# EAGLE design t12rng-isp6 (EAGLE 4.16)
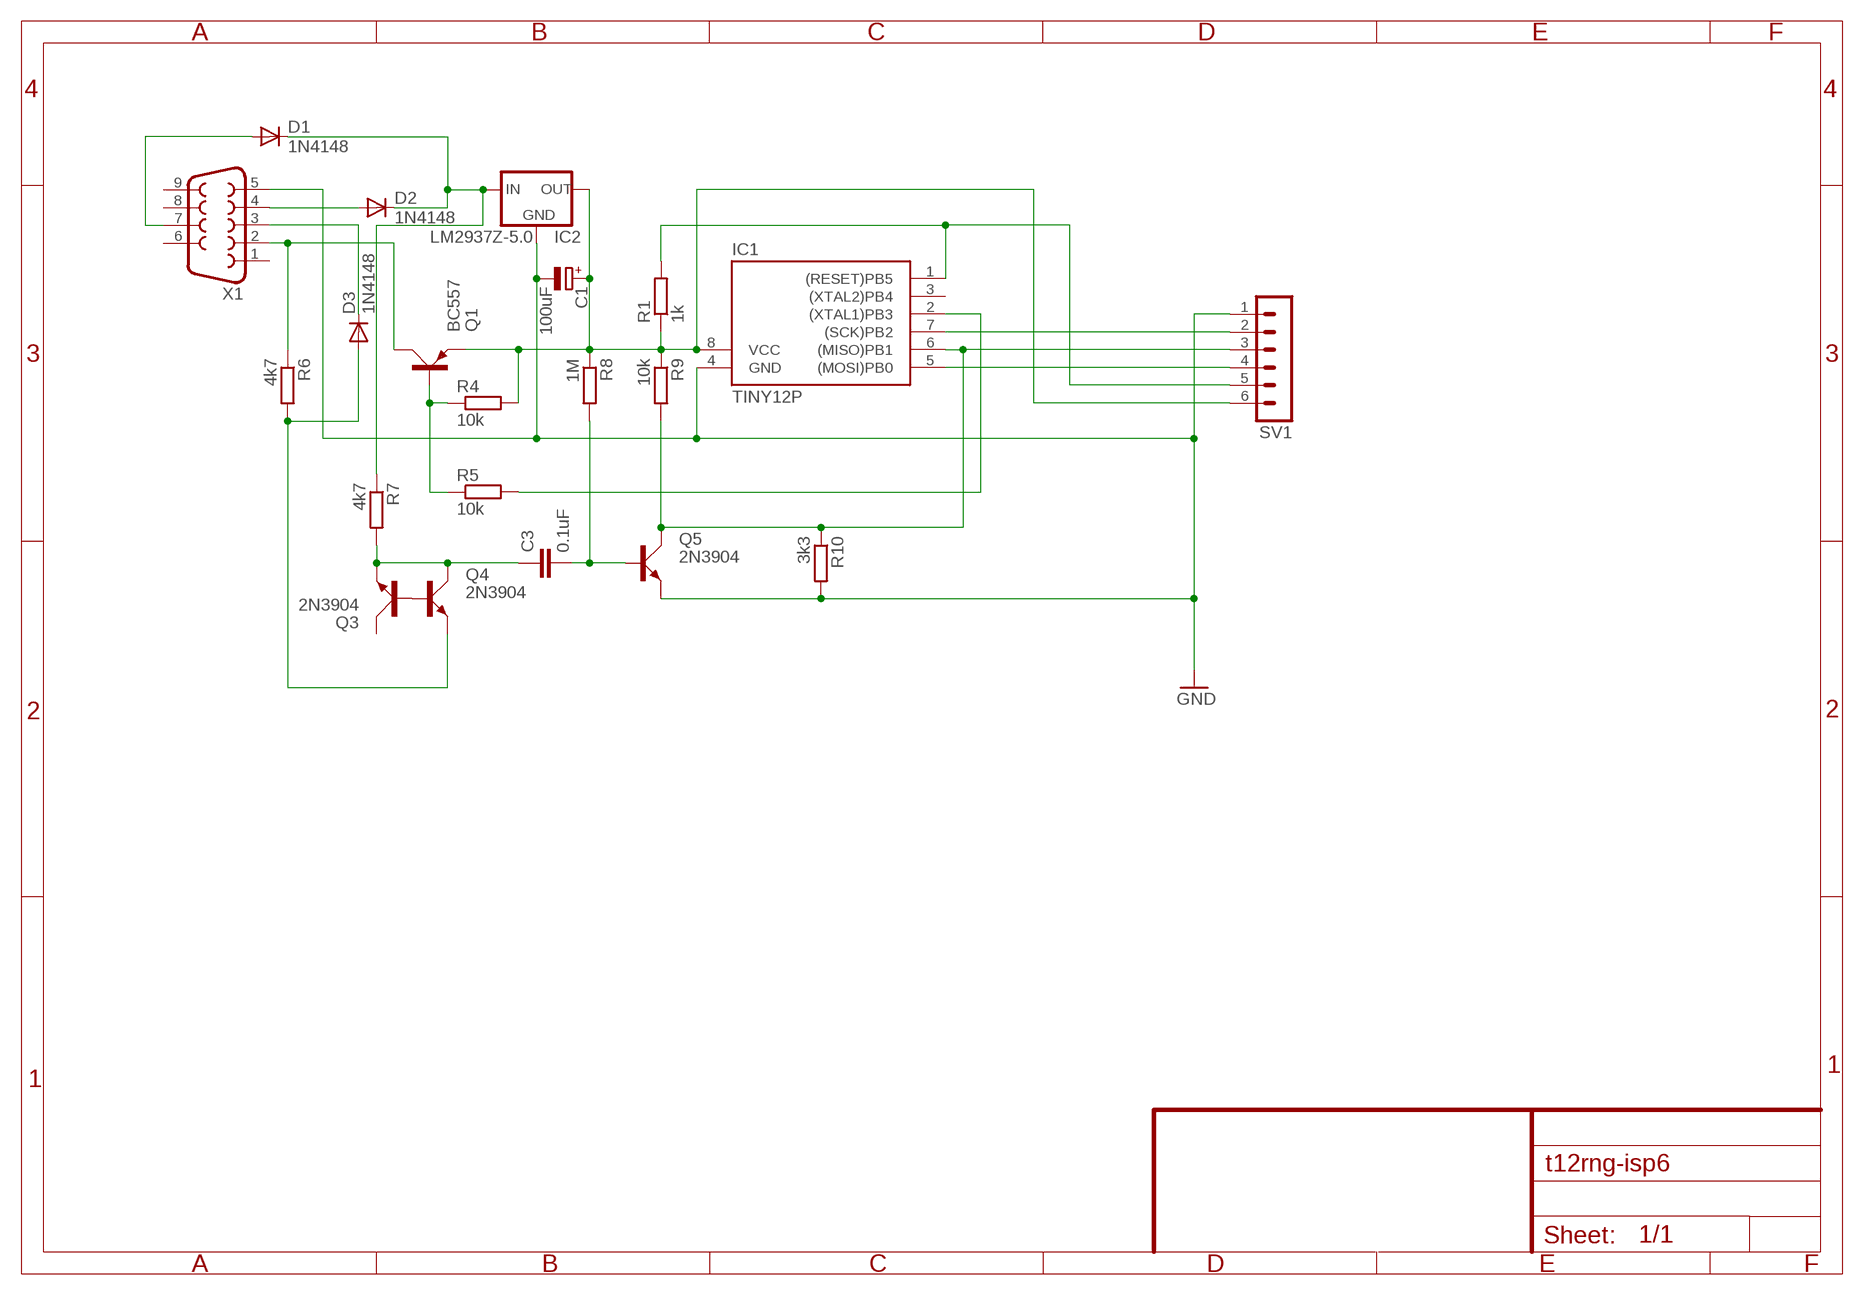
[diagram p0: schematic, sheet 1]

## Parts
C1  100uF  CPOL-EUE3.5-8  [E3,5-8]
C3  0.1uF  C-EU075-032X103  [C075-032X103]
D1  1N4148  DIODE-D-2.5  [D-2.5]
D2  1N4148  DIODE-D-2.5  [D-2.5]
D3  1N4148  DIODE-D-2.5  [D-2.5]
IC1  TINY12P  [DIL08]
IC2  LM2937Z-5.0  78LXX  [78LXX]
Q1  BC557  [SOT54A]
Q3  2N3904  [TO92D]
Q4  2N3904  [TO92D]
Q5  2N3904  [TO92D]
R1  1k  R-EU_0207/2V  [0207/2V]
R4  10k  R-EU_0207/2V  [0207/2V]
R5  10k  R-EU_0207/2V  [0207/2V]
R6  4k7  R-EU_0207/2V  [0207/2V]
R7  4k7  R-EU_0207/2V  [0207/2V]
R8  1M  R-EU_0207/2V  [0207/2V]
R9  10k  R-EU_0207/2V  [0207/2V]
R10  3k3  R-EU_0207/2V  [0207/2V]
SV1  MA06-1  [MA06-1]
X1  F09H  [F09H]

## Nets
GND: C1.- IC1.4(GND) IC2.GND Q5.E R10.2 SV1.1 X1.5
N$1: IC1.7((SCK)PB2) SV1.2
N$2: IC1.5((MOSI)PB0) SV1.4
N$3: D1.A X1.7
N$4: D2.A X1.4
N$5: D1.C D2.C IC2.IN R7.1
N$6: C1.+ IC1.8(VCC) IC2.OUT Q1.E R1.1 R4.2 R8.1 R9.1 SV1.6
N$7: IC1.1((RESET)PB5) R1.2 SV1.5
N$9: D3.A Q4.E R6.2
N$10: Q1.B R4.1 R5.1
N$11: IC1.2((XTAL1)PB3) R5.2
N$12: Q1.C R6.1 X1.2
N$13: D3.C X1.3
N$14: Q3.B Q4.B
N$15: C3.1 Q3.E Q4.C R7.2
N$17: C3.2 Q5.B R8.2
N$18: IC1.6((MISO)PB1) Q5.C R9.2 R10.1 SV1.3
Unconnected: IC1.3((XTAL2)PB4) Q3.C X1.1 X1.6 X1.8 X1.9

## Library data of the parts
C1 = rcl:CPOL-EU: POLARIZED CAPACITOR, European symbol
C3 = rcl:C-EU: CAPACITOR, European symbol
D1-D3 = diode:DIODE-: DIODE
IC1 = atmel:TINY12*: MICROCONTROLLER 1 Kbytes FLASH 64 bytes EEPROM
IC2 = v-reg:78LXX: VOLTAGE REGULATOR
Q1 = transistor-small-signal:BC557: PNP TRANSISTOR
Q3-Q5 = transistor-small-signal:2N3904: NPN TRANSISTOR
R1 R4-R10 = rcl:R-EU_: RESISTOR, European symbol
SV1 = con-lstb:MA06-1: PIN HEADER
X1 = con-subd:F09: SUB-D

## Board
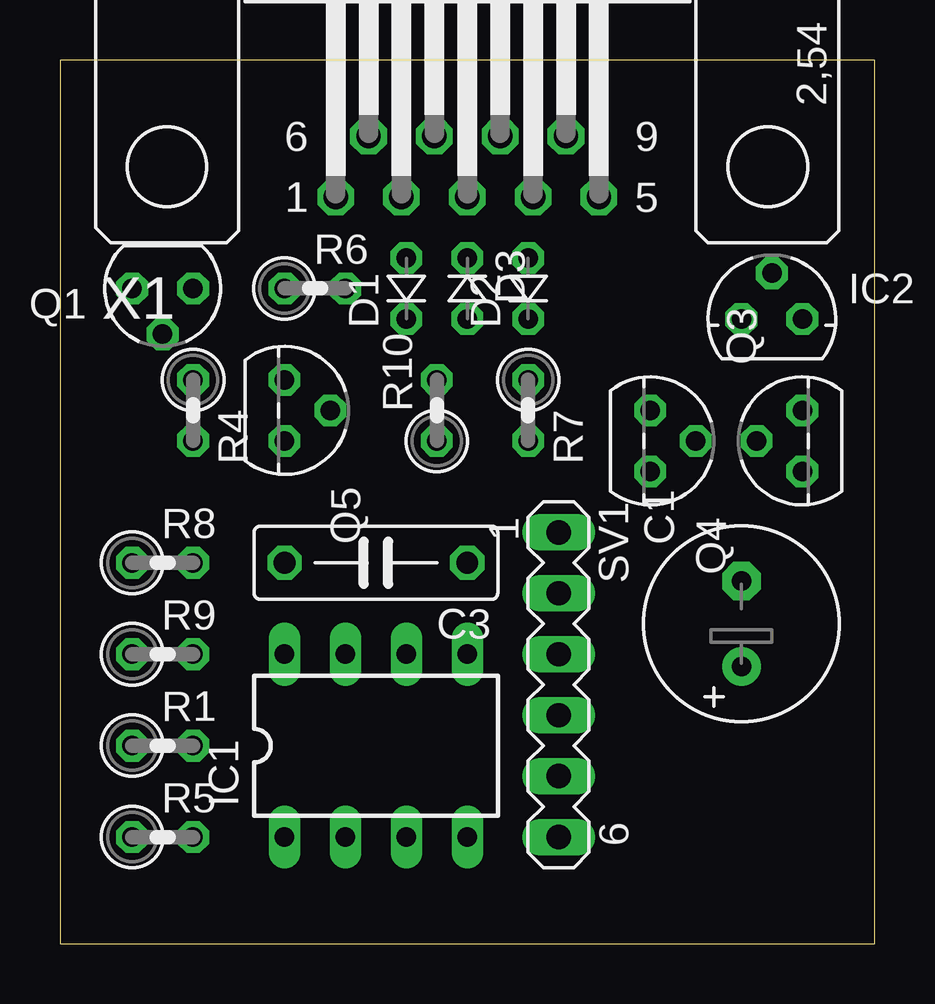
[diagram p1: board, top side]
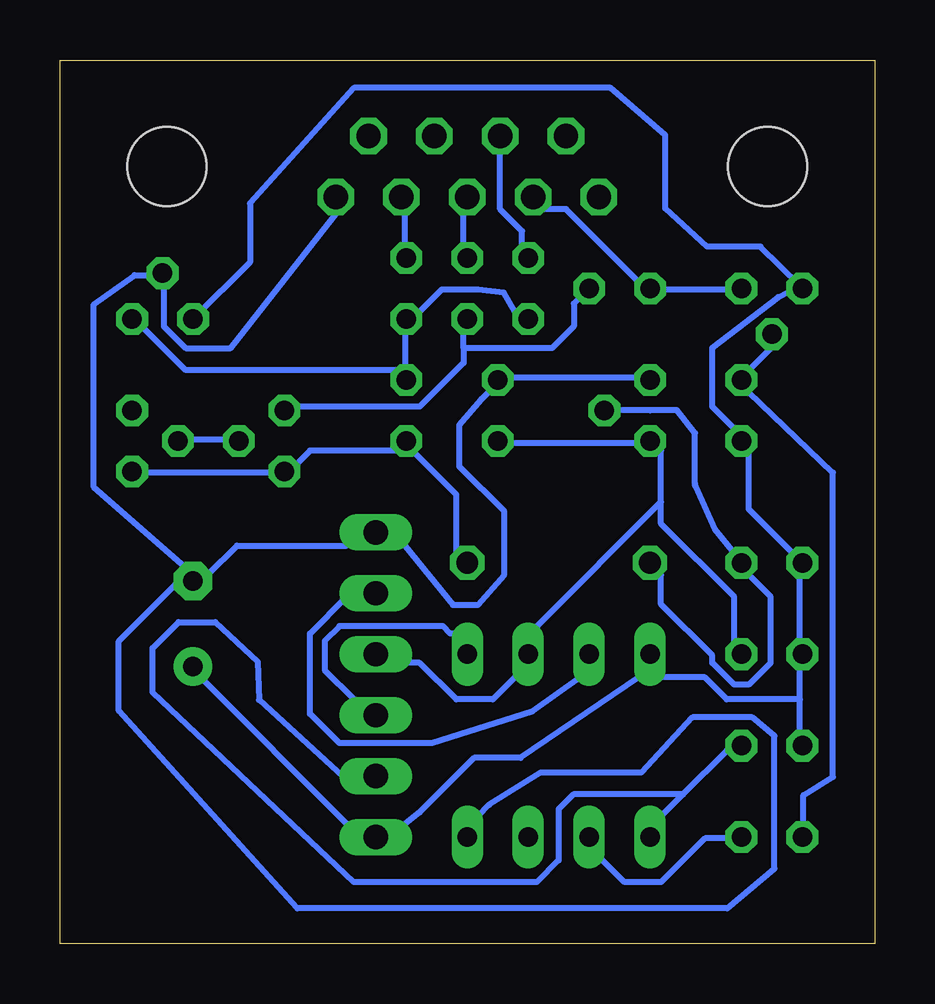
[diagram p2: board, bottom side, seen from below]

Size 33.96 x 36.82 mm. Coordinates in mm from the lower left corner, seen from the top.
Outline: 0,0 33.96,0 33.96,36.82 0,36.82 0,0
Copper layers (1*16): Top 0.035mm / dielectric 1.5mm / Bottom 0.035mm
Design rules "default": minimum track width 10mil, minimum drill 24mil, track to track 8mil, track to pad 8mil, pad to pad 8mil, via to via 8mil, smd to smd 8mil, copper to edge 40mil, drill to drill 8mil, minimum pad ring 10mil, minimum via ring 8mil, stop-mask expansion 4mil, vias tented up to drill 0mil, thermal gap 10mil

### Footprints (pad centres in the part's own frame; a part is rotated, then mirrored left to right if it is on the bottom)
E3,5-8 = drill 0.813 pad 1.6 round: + -1.778,0 | drill 0.813 pad 1.6 octagon: - 1.778,0
C075-032X103 = drill 0.914 octagon: 1 -3.81,0; 2 3.81,0
D-2.5 = drill 0.813 octagon: A 1.27,0; C -1.27,0
DIL08 = drill 0.813 long: 1 -3.81,-3.81; 2 -1.27,-3.81; 3 1.27,-3.81; 4 3.81,-3.81; 5 3.81,3.81; 6 1.27,3.81; 7 -1.27,3.81; 8 -3.81,3.81
78LXX = drill 0.813 octagon: GND 0,1.905; IN 1.27,0; OUT -1.27,0
SOT54A = drill 0.813 octagon: B 0,1.905; C -1.27,0; E 1.27,0
TO92D = drill 0.813 octagon: B 0,1.905; C 1.27,0; E -1.27,0
0207/2V = drill 0.813 octagon: 1 -1.27,0; 2 1.27,0
MA06-1 = drill 1.016 long: 1 -6.35,0; 2 -3.81,0; 3 -1.27,0; 4 1.27,0; 5 3.81,0; 6 6.35,0
F09H = drill 1.016 octagon: 1 -5.486,-1.27; 2 -2.743,-1.27; 3 0,-1.27; 4 2.743,-1.27; 5 5.486,-1.27; 6 -4.115,1.27; 7 -1.372,1.27; 8 1.372,1.27; 9 4.115,1.27 | hole 3.302: -12.522,0; 12.522,0

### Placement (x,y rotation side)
C1  28.41,13.33 90 top
C3  13.17,15.87 180 top
D1  14.44,27.3 90 top
D2  19.52,27.3 90 top
D3  16.98,27.3 270 top
IC1  13.17,8.25 0 top
IC2  29.68,26.03 0 top
Q1  4.28,27.3 180 top
Q3  30.95,20.95 90 top
Q4  24.6,20.95 270 top
Q5  9.36,22.22 270 top
R1  4.28,8.25 0 top
R4  5.55,22.22 270 top
R5  4.28,4.44 0 top
R6  10.63,27.3 0 top
R7  19.52,22.22 270 top
R8  4.28,15.87 0 top
R9  4.28,12.06 0 top
R10  15.71,22.22 90 top
SV1  20.79,10.79 270 top
X1  16.98,32.38 0 top

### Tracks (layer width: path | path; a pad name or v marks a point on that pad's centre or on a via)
GND
  Bottom 0.254: X1.5 22.31,30.6 26.84,24.81 28.71,24.81 29.63,25.73 29.63,27.55 IC2.GND 30.24,27.86 30.85,27.86 32.54,26.64 32.54,19.02 28.71,15.67 C1.- | Q5.E 9.82,23.59 15.3,23.59 R10.2 15.75,23.3 16.39,22.69 17.3,21.62 17.3,19.88 15.44,18.01 15.44,15.38 16.54,14.12 17.58,14.12 19.57,16.58 SV1.1 22.01,16.58 26.58,16.58 27.8,15.36 C1.- | IC1.4 16.52,5.3 16.07,5.78 13.93,7.13 9.72,7.13 7.59,9.42 5.1,9.42 4.17,8.66 4.17,3.13 6.15,1.47 24.07,1.47 31.51,9.7 31.51,12.61 29.03,15.08 C1.-
N$1
  Bottom 0.254: IC1.7 12.26,11.09 14.28,9.67 18.45,8.35 22.31,8.35 23.53,9.57 23.53,12.92 22.01,14.45 SV1.2
N$2
  Bottom 0.254: IC1.5 17.44,12.92 17.69,12.92 18,13.23 22.31,13.23 22.92,12.62 22.92,11.4 21.7,10.18 SV1.4
N$3
  Bottom 0.254: D1.A 14.69,29.08 14.69,29.69 15.61,30.6 X1.7
N$4
  Bottom 0.254: D2.A 19.57,29.08 19.57,30.6 X1.4
N$5
  Bottom 0.254: D1.C 15,26.34 15.45,27.13 16.52,27.25 18.05,27.25 18.96,26.34 D2.C 19.57,25.42 19.57,23.9 R7.1 19.88,23.9 28.71,23.9 30.54,25.73 IC2.IN
N$6
  Bottom 0.254: C1.+ 28.11,11.09 22.01,5 SV1.6 19.57,5 18.96,5.48 16.69,7.74 14.76,7.74 9.82,11.09 IC1.8 8.9,11.09 7.07,11.09 6.16,10.18 3.11,10.18 | 3.11,10.18 3.11,11.7 R9.1 3.11,12.62 3.11,15.36 R8.1 5.25,18.1 5.25,20.54 R4.2 5.86,21.46 6.77,22.37 6.77,24.82 4.01,26.94 3.09,27.42 | 3.11,10.18 3.11,8.66 R1.1 | 3.09,27.42 2.94,27.42 Q1.E | 3.09,27.42 4.76,29.05 6.98,29.05 8.73,30.63 8.73,33.69 11.01,35.66 21.7,35.66 26.04,30.85 26.04,28.39 IC2.OUT
N$7
  Bottom 0.254: 7.99,6.22 6.16,8.05 R1.2 | 7.99,6.22 8.9,5.3 IC1.1 | 7.99,6.22 12.56,6.22 13.17,5.61 13.17,3.48 14.08,2.56 21.7,2.56 30.11,10.48 30.11,12.31 29.02,13.4 27.48,13.4 25.71,11.74 25.67,10.16 22.16,6.96 21.69,6.96 SV1.5
N$9
  Bottom 0.254: 17.13,24.81 17.13,24.2 18.96,22.37 24.14,22.37 Q4.E | 17.13,24.81 17.13,25.42 D3.A | 17.13,24.81 13.45,24.81 12.54,25.73 12.54,26.66 R6.2
N$10
  Bottom 0.254: R5.1 2.97,5 2.97,6.19 1.73,6.95 1.73,19.63 5.25,22.98 R4.1 5.25,23.9 4.33,24.81 Q1.B
N$11
  Bottom 0.254: R5.2 6.16,4.39 7.07,4.39 8.9,2.56 10.43,2.56 11.34,3.48 IC1.2
N$12
  Bottom 0.254: Q1.C 6.16,27.25 8.9,27.25 R6.1 9.82,27.55 12.87,30.6 13.78,30.6 X1.2
N$13
  Bottom 0.254: D3.C 17.13,29.08 17.13,30.6 X1.3
N$14
  Bottom 0.254: Q4.B 26.89,21.01 28.41,21.01 Q3.B
N$15
  Bottom 0.254: Q3.E 30.54,19.63 25.06,19.63 Q4.C 24.14,19.93 23.53,20.54 19.88,20.54 R7.2 19.27,20.54 17.44,18.72 17.44,16.28 C3.1
N$17
  Bottom 0.254: Q5.B 10.73,22.23 9.36,22.22 8.24,22.23 7.49,21.27 7.49,19.17 7.46,19.05 6.65,17.26 5.86,16.28 R8.2 5.25,15.36 4.33,14.45 4.33,11.7 5.25,10.79 5.86,10.79 6.77,11.7 6.77,12.01 8.9,14.14 8.9,15.36 C3.2
N$18
  Bottom 0.254: 8.9,18.41 8.9,20.54 Q5.C 9.82,20.85 15.3,20.85 R10.1 | 8.9,18.41 8.9,17.5 5.86,14.45 5.86,12.62 R9.2 | 8.9,18.41 14.08,13.23 IC1.6 15,11.09 15.91,10.18 17.44,10.18 18.96,11.7 19.57,11.7 SV1.3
